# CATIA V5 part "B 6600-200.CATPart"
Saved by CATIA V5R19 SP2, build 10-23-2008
Part number: B 6600-200
Bounding box of the stored display mesh (mm): x -59.975 to 59.975, y -59.975 to 59.975, z 0 to 540
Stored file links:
  C:\Users\Bora\Desktop\3D Katı model\B serisi\B 6600\B 6600-200.CATPart
  C:\Program Files\Dassault Systemes\B19\intel_a\reffiles\standard\MetricThickPitch.txt
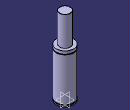
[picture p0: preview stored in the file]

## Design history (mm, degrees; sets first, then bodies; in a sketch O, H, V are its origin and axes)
Body1 (main body)
  Sketch1 on yz-plane, origin (0, 0, 0), H (0, 1, 0), V (0, 0, 1)
    point P3 (37.5, 539)
    point P5 (37.5, 539)
    point P10 (60, 312)
    point P11 (60, 317)
    point P13 (60, 317)
    point P14 (60, 312)
    line L1 (60, 0) -> (60, 8)
    line L2 (37.5, 539) -> (37.5, 337)
    arc A1 centre (36.5, 539) radius 1 from (37.5, 539) to (36.5, 540) ccw
    line L3 (56, 13) -> (56, 8)
    line L4 (60, 13) -> (60, 312)
    line L5 (60, 317) -> (60, 337)
    arc A2 centre (60, 314.5) radius 2.5 from (60, 317) to (60, 312) ccw
    line L6 (36.5, 540) -> (0, 540)
    point P15 (0, 540)
    line L7 (37.5, 337) -> (60, 337)
    line L8 (0, 0) -> (60, 0)
    line L9 (56, 13) -> (60, 13)
    line L10 (56, 8) -> (60, 8)
    coincidence: P15 V, P3 P5, P10 P14, P11 P13
    tangency: L6 A1
    horizontal: L7 H, L8 H, L9 H, L10 H
  Shaft1: profile Sketch1, axis Sketch1.V, angle 360
  Sketch2 on face of Shaft1 from Sketch1.L8, origin (0, 0, 0), H (1, 0, 0), V (0, -1, 0)
    point P1 (40, 0)
    distance P1 V = 40
  Hole1: placed by Sketch2, at (40, 0, 0) direction (0, 0, 1), diameter 8.376, depth 16, threaded "M10", thread diameter 10, thread depth 16, pitch 1.5
  CircPattern1: of Hole1, instances 4, angular step 90, axis from xy-plane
